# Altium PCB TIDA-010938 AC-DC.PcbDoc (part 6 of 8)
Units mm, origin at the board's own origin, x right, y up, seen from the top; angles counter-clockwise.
Board outline 280 x 180.15 mm, 4 copper layers (Top Layer, Layer 1, Layer 2, Bottom Layer), stack 1.787 mm thick; 723 components, 427 nets, 2244 pads, 2295 vias.
Unrouted connection lines stored in the file: 17.
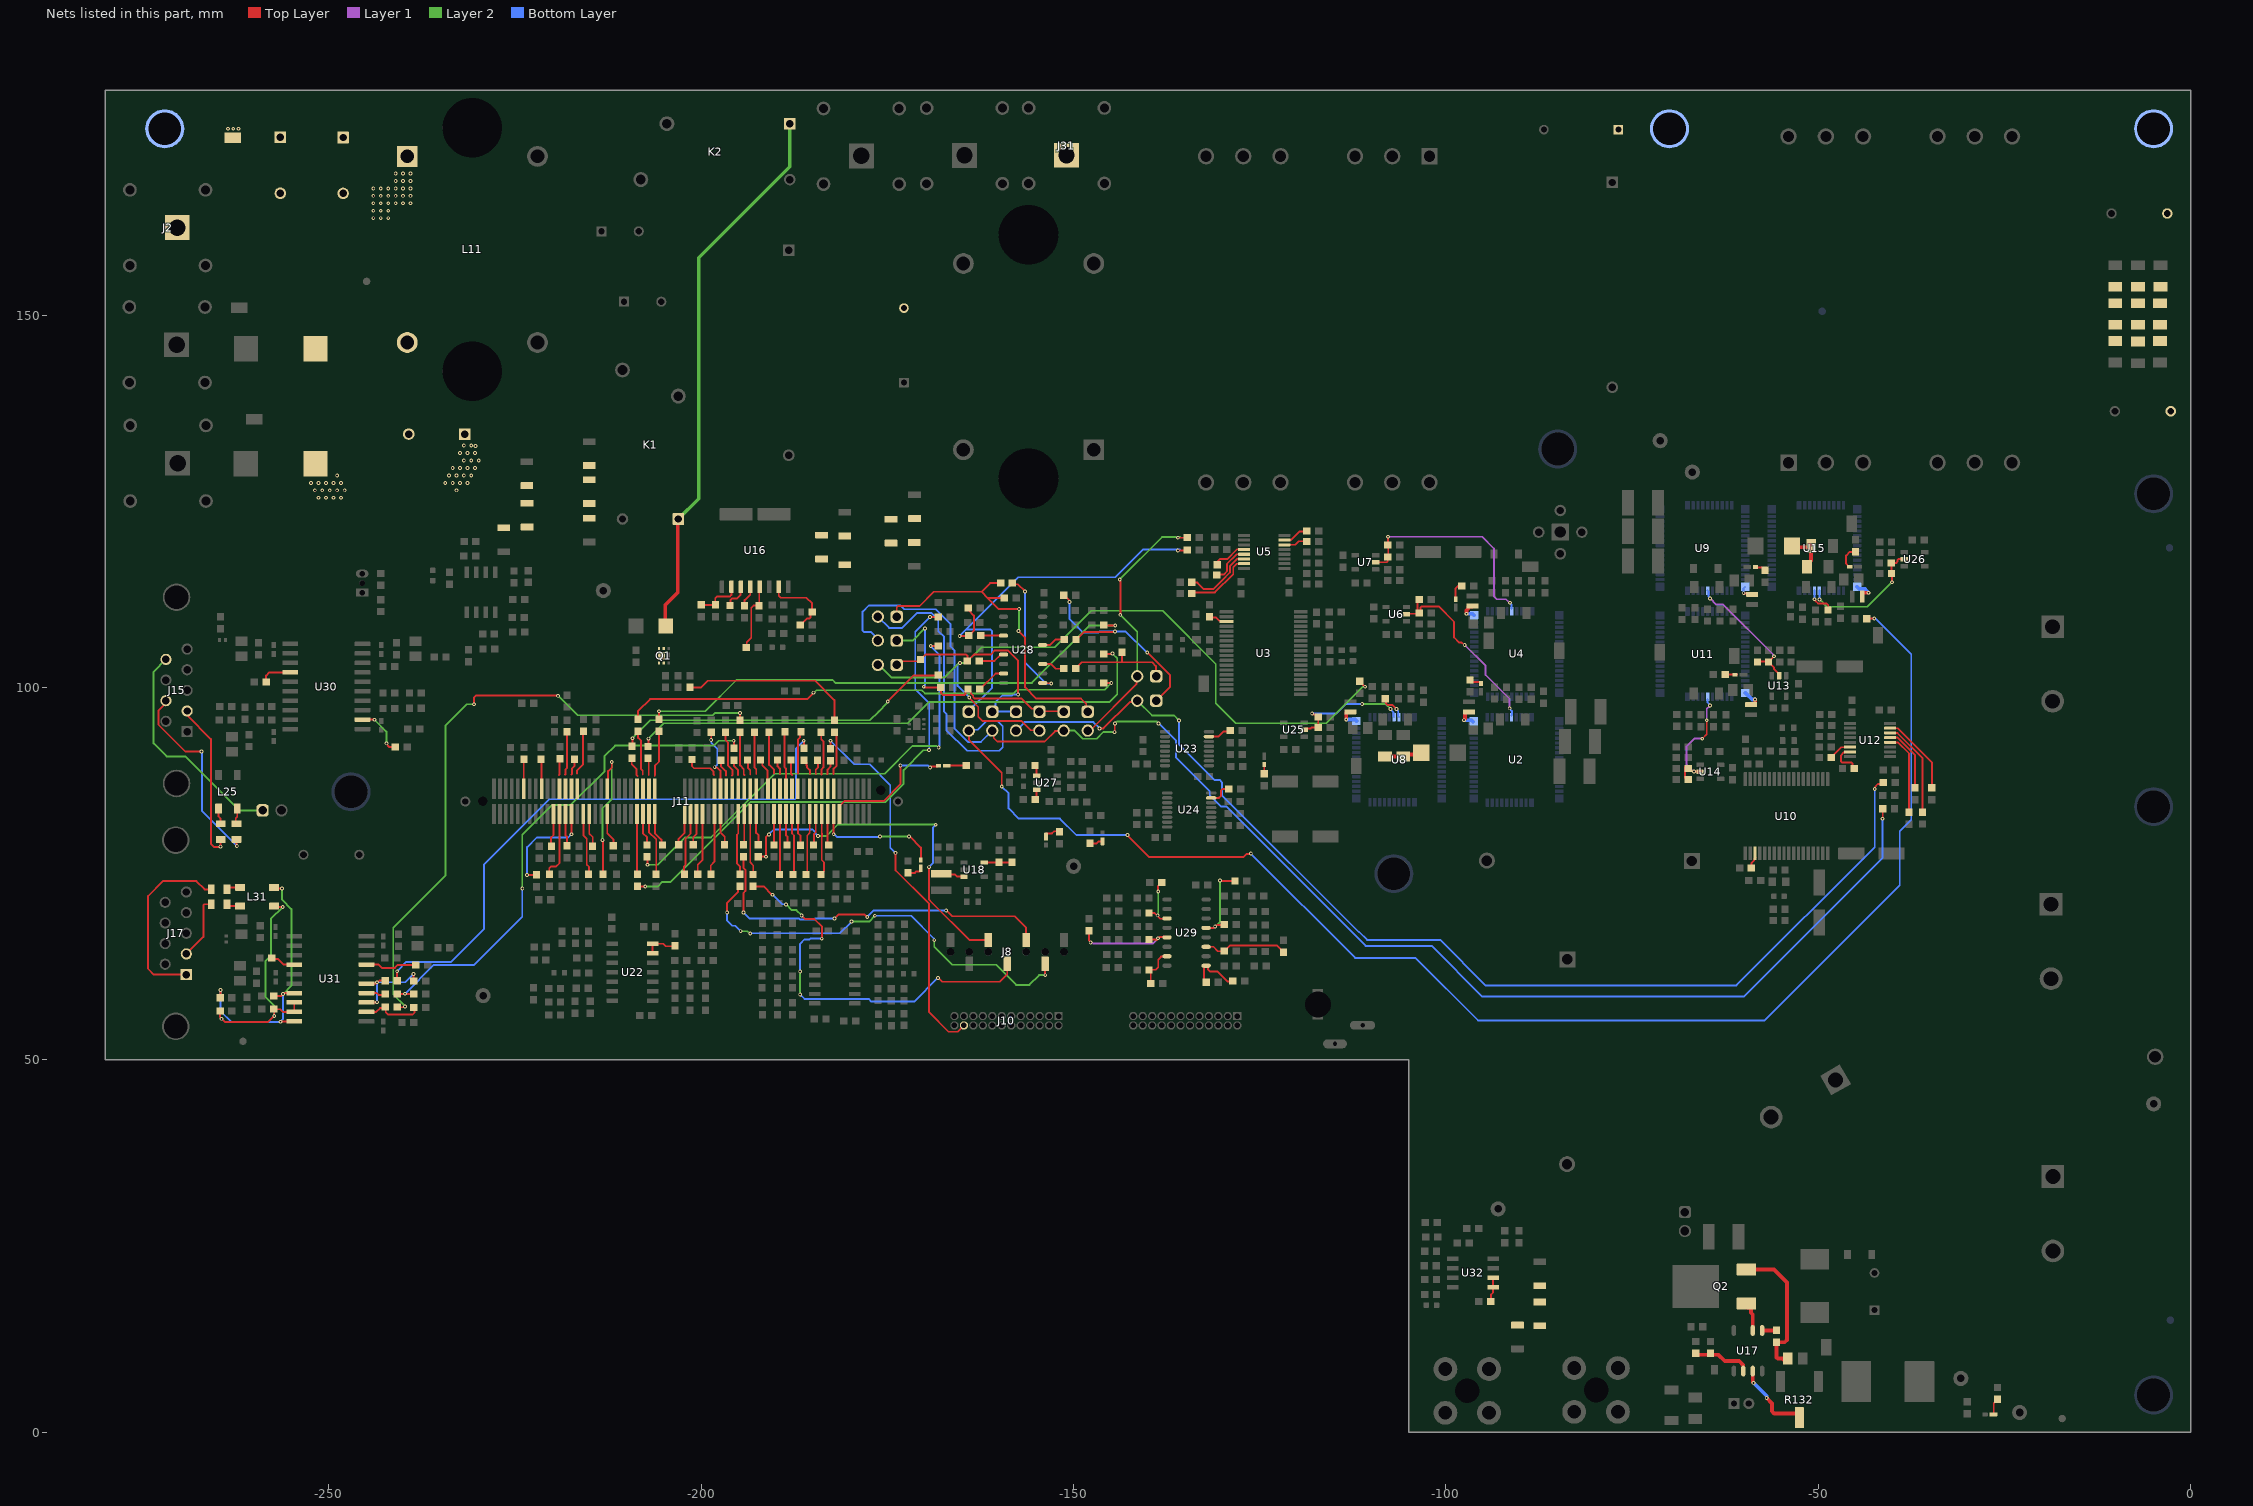
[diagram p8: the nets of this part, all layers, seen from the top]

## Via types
v1: diameter 0.508, hole 0.254, Top Layer to Bottom Layer, tented both sides, 2041 vias
v2: diameter 0.508, hole 0.254, Top Layer to Bottom Layer, 252 vias
v3: diameter 0.5, hole 0.2, Top Layer to Bottom Layer, 2 vias

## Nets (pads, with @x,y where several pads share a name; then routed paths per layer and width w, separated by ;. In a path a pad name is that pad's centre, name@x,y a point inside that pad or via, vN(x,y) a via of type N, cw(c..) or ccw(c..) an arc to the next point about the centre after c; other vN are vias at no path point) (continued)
NetC233_2: C233.2 L31.1 R288.2 U31.18 U31.19 | length 30.1
  Top Layer w0.25: C233.2@-264.578,56.566 -264.578,55.722 -263.956,55.1 -258.1,55.1 v1(-257.3,55.9) -257.3,56.47 -257.43,56.6 R288.2@-257.5,56.6 ; R288.2@-257.352,56.82 -257.332,56.8 -256.5,56.8 -256.139,56.439 -255.545,56.439 -255.5,56.484 U31.19@-255.5,56.5 ; L31.1@-257.325,70.65 -257.196,70.521 v1(-256.158,70.521) ; U31.18@-254.62,57.709 -254.62,56.52 U31.19@-254.6,56.5
  Layer 2 w0.25: v1(-257.3,55.9) -257.3,57.3 -258.492,58.492 -258.492,63.258 -257.75,64 -257.75,68.929 v1(-256.158,70.521)
  other v1: -264.374,55.517
NetC234_2: C234.2 R320.2 U31.3 U31.5 | length 13.1
  Top Layer w0.25: U31.3@-244.92,57.709 -243.509,57.709 v1@-243.5,57.7 ; U31.5@-244.92,60.249 -243.599,60.249 -243.198,60.65 -242.525,60.65 R320.2@-242.475,60.6 ; v1@-238.6,61.475 -238.6,60.607 C234.2@-238.59,60.597
  Bottom Layer w0.25: v1(-243.525,57.75) -243.513,57.763 -243.513,60.488 v1@-243.5,60.5 ; v1(-243.5,60.425) -239.725,60.425 v1(-238.6,61.55) v1@-238.6,61.6
NetC235_2: C235.2 R323.2 U31.2 | length 7.9
  Top Layer w0.25: U31.2@-244.92,56.439 -243.614,56.439 -243.1,56.953 R323.2@-242.547,56.953 ; R323.2@-242.404,57.074 -242.325,56.995 -242.325,56.375 -242.025,56.075 -238.75,56.075 -238.475,56.35 C235.2@-238.475,56.8
NetC237_1: C237.1 L31.2 R289.1 U31.17 U31.20 | length 36.6
  Top Layer w0.25: C237.1@-264.578,58.344 -264.5,58.422 v1(-264.5,59.4) ; R289.1@-257.39,58.598 -256.302,58.598 -255.9,59 U31.17@-255.4,59 ; L31.2@-257.325,73.15 -257.175,73 v1(-256.25,73) ; v1@-256.4,55.1 -256.331,55.169 U31.20@-254.62,55.169
  Layer 2 w0.25: v1(-256.25,73) -256.25,71.5 -255,70.25 -255,59.952 v1(-256.123,58.828)
  Bottom Layer w0.25: v1(-264.5,59.4) -264.5,56.5 -263.1,55.1 v1@-256.5,55.1 ; v1@-256.5,55.2 -256.461,55.2 -256.123,55.537 v1(-256.123,58.828)
  other v1: -256.474,55.117
NetD1_2: D1.2 R7.2 R41.2 | length 5.1
  Top Layer w0.25: R7.2@-105.75,90.725 R7.2@-105.475,91 ; D1.2@-103.55,91 D1.2@-103.325,91.225
  Top Layer w0.5: R41.2@-108.2,90.725 R7.2@-105.75,90.725 ; R7.2@-105.475,91 D1.2@-103.55,91
NetD4_2: D4.2 R17.2 | length 1.7
  Top Layer w0.25: R17.2@-96.8,101 -96.55,100.75 -95.425,100.75 -95.3,100.625 D4.2@-95.3,100.545
NetD7_2: D7.2 R53.2 R55.2 | length 5.2
  Top Layer w0.5: D7.2@-53.29,118.721 -53.19,118.821 -51,118.821 -51,117.011 -51.54,116.471 R53.2@-51.54,116.196
NetD10_2: D10.2 R42.2 | length 2.4
  Top Layer w0.25: D10.2@-98.7,111.845 -98.7,113.3 -98.4,113.6 R42.2@-97.9,113.6
NetD16_1: D16.1 R100.1 | length 2.4
  Top Layer w0.25: D16.1@-26.459,2.399 -26.459,3.92 R100.1@-25.851,4.528
NetD17_1: D17.1 R101.2 | length 1.8
  Top Layer w0.25: D17.1@-153.7,80.3 -153.6,80.4 -152.9,80.4 -152.6,80.7 R101.2@-152.1,80.7
NetD18_1: D18.1 R102.2 | length 1.8
  Top Layer w0.25: R102.2@-147.8,79.075 -146.879,79.075 -146.617,79.337 D18.1@-146.117,79.337
NetD23_1: D23.1 R70.2 | length 1.8
  Top Layer w0.25: R70.2@-172.2,75.1 -171.3,75.1 -171.1,75.3 -170.6,75.3 D23.1@-170.5,75.4
NetD23_2: D23.2 J11.107 | length 16.7
  Top Layer w0.25: J11.107@-182.207,82.998 -182.204,82.995 -182.204,80.303 v1(-182.2,80.3) ; v1@-172,80 -170.5,78.5 D23.2@-170.5,77
  Layer 2 w0.25: v1(-175.975,79.975) v1(-172.075,79.975) -172.025,79.975 v1@-172,80
  Bottom Layer w0.25: v1(-182.2,80.3) -182.13,80.3 -181.776,79.946 v1@-175.954,79.946
NetD24_1: D24.1 R76.2 | length 2.7
  Top Layer w0.25: D24.1@-167.03,89.5 R76.2@-164.379,89.5
NetD24_2: D24.2 J11.109 | length 18.4
  Top Layer w0.25: J11.109@-181.407,82.998 -181.407,84.093 -180.75,84.75 -175.5,84.75 -173.25,87 v1(-173.25,89.504) ; v1(-169.25,89.25) -169.18,89.25 -169.023,89.408 -168.237,89.408 D24.2@-168.145,89.5 D24.2@-168.245,89.5
  Bottom Layer w0.25: v1(-173.25,89.504) -169.504,89.504 v1(-169.25,89.25)
NetD25_2: D25.2 R43.2 | length 1.3
  Top Layer w0.25: R43.2@-124.4,88.4 D25.2@-124.4,89.655
NetD26_2: D26.2 R51.2 | length 1.2
  Top Layer w0.25: D26.2@-58.19,116.121 -57.69,116.121 -57.665,116.096 -57.54,116.096 -57.29,115.846 -57.29,115.721 R51.2@-57.19,115.721
NetD27_2: D27.2 R52.2 | length 1.6
  Top Layer w0.25: R52.2@-62.79,101.721 R52.2@-62.785,101.721 ; R52.2@-62.49,101.721 D27.2@-60.935,101.721
NetD28_2: D28.2 R115.2 | length 3.2
  Top Layer w0.25: D28.2@-45.805,116.221 -45.905,116.221 -46.29,116.606 -46.29,117.71 -45.8,118.2 R115.2@-45,118.2
NetF1_1: F1.1 L11.AII R78.2 R82.2
NetF2_1: F2.1 L11.AI R81.2 R82.1
  other v1: -244,163 -243,163 -242,163 -244,164 -243,164 -242,164 -244,165 -243,165 -242,165 -241,165 -240,165 -239,165 -244,166 -243,166 -242,166 -241,166 -240,166 -239,166 -244,167 -243,167 -242,167 -241,167 -240,167 -239,167 -241,168 -240,168 -239,168 -241,169 -240,169 -239,169
  other v2: -251.352,125.464 -250.352,125.464 -249.352,125.464 -248.352,125.464 -251.852,126.464 -250.852,126.464 -249.852,126.464 -248.852,126.464 -247.852,126.464 -232.852,126.464 -252.352,127.464 -251.352,127.464 -250.352,127.464 -249.352,127.464 -248.352,127.464 -234.352,127.464 -233.352,127.464 -232.352,127.464 -231.352,127.464 -248.852,128.464 -233.852,128.464 -232.852,128.464 -231.852,128.464 -230.852,128.464 -233.352,129.464 -232.352,129.464 -231.352,129.464 -230.352,129.464 -231.852,130.464 -230.852,130.464 -229.852,130.464 -232.352,131.464 -231.352,131.464 -230.352,131.464 -230.298,132.434 -231.852,132.464 -230.852,132.464
NetJ4_1: J4.1 J21.1 J23.1 R146.2 R249.2 | length 31.3
  Top Layer w0.25: J4.1@-173.73,103.525 -170.775,103.525 R249.2@-170.55,103.75 -170.55,103.775 -170.2,104.125 -170.175,104.125 -169.881,104.419 -164.404,104.419 -164.258,104.273 R146.2@-164.258,103.556 -164.233,103.556 -163.37,104.419 -161.115,104.419 -160.569,104.965 -158.822,104.965 -157.451,103.594 -157.451,99.089 v1(-157.43,99.068) ; J21.1@-161.413,96.749 J21.1@-161.375,96.787
  Bottom Layer w0.25: J23.1@-158.256,97.283 J23.1@-158.243,97.296 ; J23.1@-157.721,96.749 J21.1@-160.913,96.749 -160.5,97.162 -160.5,98 -159.578,98.922 -158.256,98.922 -158.109,99.068 v1(-157.43,99.068)
NetJ5_1: J5.1 R154.2 R243.2 | length 14.5
  Top Layer w0.25: R154.2@-149.729,102.565 -149.704,102.565 -148.891,103.378 -143.532,103.378 ; R243.2@-143.5,104.5 -143.5,103.41 -143.532,103.378 ; J5.1@-138.934,100.889 -138.934,102.878 -139.434,103.378 -143.532,103.378
NetJ8_2: J8.2 R57.1 | length 56.2
  Top Layer w0.25: v1@-196.5,69.8 -196.5,71.1 -195.029,72.571 -195.029,73.071 R57.1@-194.8,73.3 ; J8.2@-153.82,62.9 -153.82,61.42 v1@-153.8,61.4
  Layer 2 w0.25: v1(-194.684,67.28) -193.774,67.28 -193.493,67 v1@-193.4,67 ; v1@-179.79,68.574 -177.449,68.574 v1(-176.675,69.349) ; v1(-168.698,66.074) -168.698,65.198 -166.272,62.772 -160.406,62.772 -157.705,60.071 -155.927,60.071 -154.624,61.374 v1(-153.798,61.374)
  Bottom Layer w0.25: v1(-196.498,69.774) -196.498,68.698 -195.814,68.014 -195.417,68.014 v1(-194.684,67.28) ; v1(-193.398,66.974) -193.369,67.003 -181.369,67.003 v1(-179.798,68.574) ; v1(-176.675,69.349) -171.801,69.349 -168.747,66.295 -168.747,66.124 v1(-168.698,66.074)
NetJ8_3: J8.3 R210.1 | length 49.4
  Top Layer w0.25: R210.1@-194.325,77.3 -194.325,75.789 -194.05,75.514 -194.05,72.686 -194.3,72.436 v1@-194.3,69.8 ; v1(-182.098,68.974) -181.572,69.5 -178.024,69.5 v1(-177.698,69.174) ; v1@-167.1,70.1 -166.281,69.281 -157.881,69.281 -156.36,67.76 J8.3@-156.36,66.105
  Bottom Layer w0.25: v1(-194.298,69.774) -193.528,69.004 -186.876,69.004 -186.717,68.845 -184.807,68.845 -184.648,69.004 -182.104,69.004 v1@-182.1,69 ; v1@-177.7,69.2 -176.826,70.074 v1(-167.098,70.074)
NetJ8_4: J8.4 R212.1 | length 54.6
  Top Layer w0.25: R212.1@-193.02,73.291 -191.618,73.291 -190.527,72.2 v1@-190.4,72.2 ; v1(-186.498,69.374) -186.024,68.9 -184.776,68.9 -183.765,67.889 -183.765,66.335 v1@-183.8,66.3 ; v1(-168.2,61) -168.134,61 -167.634,60.5 -159.9,60.5 -158.9,61.5 J8.4@-158.9,62.9
  Layer 2 w0.25: v1(-188.598,70.874) -187.836,70.112 -187.212,70.112 v1@-186.5,69.4 ; v1@-186.7,61.9 -186.698,61.898 v1(-186.698,61.874) v1(-186.698,58.774)
  Bottom Layer w0.25: v1(-190.398,72.174) -189.124,70.9 v1@-188.6,70.9 ; v1(-186.698,58.774) -186.115,58.191 -177.517,58.191 -177.161,57.836 -171.364,57.836 v1(-168.2,61) ; v1(-186.698,61.874) -186.698,65.602 -186.136,66.164 -185.456,66.164 -185.346,66.274 v1(-183.798,66.274)
NetJ8_5: J8.5 R214.1 | length 48.6
  Top Layer w0.25: R214.1@-192.325,77.3 v1@-191.3,77.3 ; v1(-191.298,77.274) -191.298,79.902 v1@-190.9,80.3 ; v1(-169.398,75.874) -169.398,71.5 -169,71.102 ; -169,71.1 -169,71.102 ; J8.5@-161.44,66.105 -164.003,66.105 -168.999,71.101
  Layer 2 w0.25: v1(-184.321,80.042) -183.206,80.042 -181.648,81.6 v1@-168.5,81.6
  Bottom Layer w0.25: v1(-190.898,80.274) -190.243,80.929 -185.029,80.929 -184.724,80.624 -184.724,80.515 -184.321,80.112 v1(-184.321,80.042) ; v1@-169.4,75.9 -168.846,76.454 -168.846,81.226 v1(-168.498,81.574)
NetJ11_12: J11.12 R174.1 | length 4
  Top Layer w0.25: J11.12@-223.807,86.398 -223.807,90.393 R174.1@-223.775,90.425
NetJ11_18: J11.18 R179.1 | length 4
  Top Layer w0.25: R179.1@-221.425,90.35 -221.407,90.332 J11.18@-221.407,86.398
NetJ11_21: J11.21 R183.1 | length 4.5
  Top Layer w0.25: R183.1@-220.125,78.675 -220.125,79.875 -219.807,80.193 J11.21@-219.807,82.998
NetJ11_23: J11.23 R182.1 | length 8.9
  Top Layer w0.25: R182.1@-220.425,75.2 -220.375,75.25 -220.375,75.7 -220.1,75.975 -219.45,75.975 -219.007,76.418 J11.23@-219.007,82.998 ; R182.1@-220.411,74.864 R182.1@-220.375,74.9 R182.1@-220.329,74.946
NetJ11_24: J11.24 R181.2 | length 2.3
  Top Layer w0.25: -219.1,88.225 -219.007,88.318 -219.007,90.368 R181.2@-218.95,90.425
NetJ11_25: J11.25 R184.1 | length 4.5
  Top Layer w0.25: J11.25@-218.207,82.998 -218.207,80.182 -218,79.975 -218,78.9 R184.1@-217.8,78.7 ; R184.1@-217.979,78.489 R184.1@-217.954,78.514
NetJ11_26: J11.26 R180.2 | length 5.8
  Top Layer w0.25: -218.25,88.3 -218.225,88.325 -218.225,88.975 -218.025,89.175 R180.2@-218.025,94.025
NetJ11_27: J11.27 R67.1 | length 14.4
  Top Layer w0.25: v1(-223.364,74.828) R67.1@-222.119,74.828 ; J11.27@-217.407,82.998 -217.407,80.302 v1(-217.395,80.289)
  Bottom Layer w0.25: v1(-223.364,74.828) -223.364,78.562 -222.068,79.858 -217.853,79.858 -217.421,80.289 v1(-217.395,80.289)
NetJ11_28: J11.28 R178.2 | length 2.3
  Top Layer w0.25: -217.425,88.275 -217.35,88.35 -217.35,89.1 -216.975,89.475 R178.2@-216.975,90.375
NetJ11_30: J11.30 R176.2 | length 6
  Top Layer w0.25: -216.65,88.45 -216.65,88.875 -215.85,89.675 -215.85,94.05 R176.2@-215.8,94.1
NetJ11_31: J11.31 R186.2 | length 7.9
  Top Layer w0.25: J11.31@-215.807,82.998 -215.807,80.132 -215.35,79.675 -215.35,76.2 -215.05,75.9 R186.2@-215.05,75.375
NetJ11_33: J11.33 R187.2 | length 4.4
  Top Layer w0.25: J11.33@-215.007,82.998 -215.007,80.382 -214.55,79.925 R187.2@-214.55,78.825
NetJ11_39: J11.39 R189.2 | length 4.4
  Top Layer w0.25: J11.39@-212.607,82.998 -212.607,80.407 -211.75,79.55 R189.2@-211.75,79
NetJ11_40: J11.40 R188.2 | length 19.4
  Top Layer w0.25: R188.2@-213.153,74.916 v1@-213.153,79.403 ; J11.40@-212.607,86.398 -212.482,86.523 -212.482,88.768 -212,89.25 v1(-212,90)
  Layer 2 w0.25: v1(-213.25,79.5) -213.25,83.75 -212,85 v1(-212,90)
NetJ11_49: J11.49 R190.2 | length 8.3
  Top Layer w0.25: R190.2@-208.65,75.025 -208.607,75.068 J11.49@-208.607,82.998 ; R190.2@-208.607,75.057 R190.2@-208.4,74.85
NetJ11_50: J11.50 R194.2 | length 2.7
  Top Layer w0.25: R194.2@-209.25,90.5 -209.3,90.45 -209.3,89.675 -208.65,89.025 -208.65,88.225 -208.55,88.125
NetJ11_51: J11.51 R192.2 | length 4.2
  Top Layer w0.25: J11.51@-207.807,82.998 -207.807,80.457 -207.25,79.9 R192.2@-207.25,79
NetJ11_52: J11.52 R196.2 | length 6.3
  Top Layer w0.25: R196.2@-208.45,94.4 -208.45,93.225 -208.05,92.825 -208.05,89.025 -207.825,88.8 -207.825,88.325
NetJ11_53: J11.53 R198.2 | length 8.3
  Top Layer w0.25: J11.53@-207.007,82.998 -207.007,80.582 -206.025,79.6 R198.2@-206.025,75.075
NetJ11_54: J11.54 R191.1 | length 2.3
  Top Layer w0.25: R191.1@-207.1,90.475 -207.025,90.4 -207.025,88.25
NetJ11_55: J11.55 R199.2 | length 4.5
  Top Layer w0.25: J11.55@-206.207,82.998 -206.207,80.457 -205.329,79.579 -205.329,79.004 R199.2@-205.225,78.9
NetJ11_56: J11.56 R193.1 | length 6.1
  Top Layer w0.25: -206.225,88.125 -206.207,88.143 ; -206.2,88.275 -206.2,89.475 -205.65,90.025 R193.1@-205.65,94.125
NetJ11_57: J11.57 R200.2 | length 4.2
  Top Layer w0.25: R200.2@-203.025,79.15 -203.025,79.675 -202.207,80.493 J11.57@-202.207,82.998
NetJ11_59: J11.59 R201.2 | length 8
  Top Layer w0.25: R201.2@-202.3,75.325 -202.3,75.95 -202.075,76.175 -202.075,79.725 -201.407,80.393 J11.59@-201.407,82.998
NetJ11_61: J11.61 R195.1 | length 4.4
  Top Layer w0.25: R195.1@-201.05,78.825 R195.1@-201.05,78.875 -201.05,79.9 -200.607,80.343 J11.61@-200.607,82.998
NetJ11_63: J11.63 R197.1 | length 8
  Top Layer w0.25: R197.1@-200.516,75.325 -200.516,75.334 -200.45,75.4 -200.45,76.204 -199.807,76.847 J11.63@-199.807,82.998
NetJ11_67: J11.67 R203.2 | length 8.2
  Top Layer w0.25: R203.2@-198.825,75.025 -198.7,75.15 -198.7,76.1 -198.207,76.593 J11.67@-198.207,82.998
NetJ11_68: J11.68 R204.1 | length 4.6
  Top Layer w0.25: R204.1@-201.219,90.326 -201.219,89.419 -200.95,89.15 -198.798,89.15 -198.329,88.681 -198.329,88.329 -198.225,88.225
NetJ11_69: J11.69 R205.2 | length 4.2
  Top Layer w0.25: J11.69@-197.407,82.998 -197.407,80.557 -196.825,79.975 R205.2@-196.825,79.025
NetJ11_70: J11.70 R206.1 | length 8.5
  Top Layer w0.25: v1@-198.65,93 -198.641,93.009 R206.1@-198.641,93.998 ; v1(-198.175,89.3) -198.126,89.251 -197.826,89.251 -197.407,88.832 J11.70@-197.407,86.398
  Layer 1 w0.25: v1(-198.65,92.95) v1@-198.643,92.943
  Bottom Layer w0.25: v1@-198.643,92.943 -198.643,92.568 -197.825,91.75 -197.825,89.65 v1(-198.175,89.3)
NetJ11_72: J11.72 R207.1 | length 2.3
  Top Layer w0.25: R207.1@-197.338,90.226 -197.338,89.438 -196.675,88.775 -196.675,88.175
NetJ11_74: J11.74 R208.1 | length 6.2
  Top Layer w0.25: R208.1@-196.699,93.976 -196.699,92.924 -196.375,92.6 -196.375,89.5 -195.807,88.932 -195.807,88.218 -195.875,88.15
NetJ11_75: J11.75 R57.2 | length 8.3
  Top Layer w0.25: J11.75@-195.007,82.998 -195.007,80.393 -195.2,80.2 -195.2,76.4 -194.8,76 R57.2@-194.8,74.9
NetJ11_76: J11.76 R209.1 | length 2.2
  Top Layer w0.25: R209.1@-195.56,90.226 -195.56,89.435 -195.022,88.897 -195.022,88.278 -195.075,88.225
NetJ11_77: J11.77 R210.2 | length 4
  Top Layer w0.25: J11.77@-194.207,82.998 -194.207,79.157 R210.2@-194.075,79.025
NetJ11_78: J11.78 R211.1 | length 6
  Top Layer w0.25: R211.1@-194.758,93.998 -194.758,89.533 -194.275,89.05 -194.275,88.325 -194.175,88.225
NetJ11_79: J11.79 R212.2 | length 7.9
  Top Layer w0.25: J11.79@-193.407,82.998 -193.407,76.507 -193,76.1 R212.2@-193,75.3
NetJ11_80: J11.80 R213.1 | length 2.1
  Top Layer w0.25: R213.1@-193.782,90.264 -193.725,90.207 -193.725,89.225 -193.4,88.9 -193.4,88.3
NetJ11_81: J11.81 R214.2 | length 4.2
  Top Layer w0.25: J11.81@-192.607,82.998 -192.607,80.484 -192.275,80.152 -192.275,79.125 R214.2@-192.4,79
NetJ11_82: J11.82 R215.1 | length 5.7
  Top Layer w0.25: R215.1@-192.816,93.998 -192.816,89.241 -192.6,89.025 -192.6,88.4
NetJ11_86: J11.86 R216.1 | length 4.3
  Top Layer w0.25: R216.1@-192.004,90.264 -191.785,90.045 -191.785,89.535 -191.105,88.855 -191.105,86.496 J11.86@-191.007,86.398
NetJ11_87: J11.87 R217.2 | length 3.9
  Top Layer w0.25: R217.2@-190.225,79.1 -190.207,79.118 J11.87@-190.207,82.998
NetJ11_88: J11.88 R218.1 | length 5.8
  Top Layer w0.25: R218.1@-190.875,93.975 -190.875,89.6 -190.2,88.925 -190.2,88.425
NetJ11_89: J11.89 R219.2 | length 8
  Top Layer w0.25: R219.2@-189.475,75.075 -189.407,75.143 J11.89@-189.407,82.998
NetJ11_90: J11.90 R220.1 | length 2
  Top Layer w0.25: R220.1@-189.718,90.264 -189.718,89.393 -189.425,89.1 -189.425,88.375
NetJ11_91: J11.91 R221.2 | length 4.1
  Top Layer w0.25: J11.91@-188.607,82.998 -188.607,80.182 -188.4,79.975 R221.2@-188.4,79
NetJ11_92: J11.92 R222.1 | length 7.8
  Top Layer w0.25: J11.92@-188.607,86.398 -188.607,89.102 -188.8,89.295 -188.8,93.775 R222.1@-188.55,94.025
NetJ11_93: J11.93 R223.2 | length 8
  Top Layer w0.25: J11.93@-187.807,82.998 -187.807,80.407 -187.525,80.125 -187.525,75.266 -187.566,75.225 R223.2@-187.65,75.225
NetJ11_94: J11.94 R224.1 | length 2.1
  Top Layer w0.25: R224.1@-187.94,90.264 -187.94,88.405 -187.785,88.25 -187.775,88.25
NetJ11_95: J11.95 R225.2 | length 4.1
  Top Layer w0.25: J11.95@-187.007,82.998 -187.007,80.457 -186.675,80.125 R225.2@-186.675,79.075
NetJ11_96: J11.96 R226.1 | length 5.8
  Top Layer w0.25: -187,88.425 -187,93 -186.704,93.296 -186.704,93.93 R226.1@-186.609,94.025
NetJ11_99: J11.99 R227.2 | length 8.3
  Top Layer w0.25: R227.2@-185.85,74.85 -185.75,74.95 -185.75,80.125 -185.407,80.468 J11.99@-185.407,82.998
NetJ11_100: J11.100 R228.1 | length 2.1
  Top Layer w0.25: R228.1@-186.162,90.226 -185.839,89.903 -185.839,89.544 -185.803,89.508 -185.803,89.298 -185.4,88.895 -185.4,88.4
NetJ11_101: J11.101 R229.2 | length 4
  Top Layer w0.25: R229.2@-184.85,79.1 -184.85,80.325 -184.607,80.568 J11.101@-184.607,82.998
NetJ11_102: J11.102 R230.1 | length 1.9
  Top Layer w0.25: -184.575,88.35 -184.607,88.382 -184.607,88.943 -184.325,89.225 R230.1@-184.325,90.1
NetJ11_103: J11.103 R231.2 | length 8.4
  Top Layer w0.25: R231.2@-183.9,74.975 -183.817,74.975 -183.526,75.266 -183.526,75.386 -183.5,75.412 -183.5,76.527 -183.807,76.834 -183.807,79.917 -183.769,79.955 -183.769,80.393 -183.807,80.431 J11.103@-183.807,82.998
NetJ11_104: J11.104 R232.1 | length 5.9
  Top Layer w0.25: R232.1@-183.876,93.998 -183.876,93.051 -183.575,92.75 -183.575,89.275 -183.825,89.025 -183.825,88.325
NetJ11_105: J11.105 R233.2 | length 3.9
  Top Layer w0.25: J11.105@-183.007,82.998 -183.007,79.207 R233.2@-182.925,79.125
NetJ11_106: J11.106 R234.1 | length 2
  Top Layer w0.25: -183.075,88.375 -183.047,88.375 -183.025,88.397 -183.025,88.975 -182.65,89.35 -182.65,90.144 R234.1@-182.606,90.188
NetJ11_108: J11.108 R236.1 | length 5.9
  Top Layer w0.25: -182.25,88.375 -182.222,88.375 -182.2,88.397 -182.2,89.1 -181.8,89.5 -181.8,93.7 R236.1@-182.098,93.998
NetJ13_1: J13.1 R175.2 R241.2 | length 30.1
  Top Layer w0.25: R241.2@-151.3,112.375 -151.275,112.375 -150.596,111.696 -150.596,111.516 v1(-150.547,111.467) ; R175.2@-149.666,106.426 -149.641,106.426 -148.625,107.442 v1@-144.471,107.442 ; v1(-140.107,104.711) -137.029,101.632 -137.029,100.101 J13.1@-138.909,98.222
  Bottom Layer w0.25: v1(-150.547,111.467) -150.547,109.214 -148.7,107.367 -146.679,107.367 -146.541,107.505 v1(-144.451,107.505) -142.985,107.505 v1@-140.128,104.648
NetJ14_1: J14.1 J24.1 J25.1 R148.2 R247.2 | length 33.7
  Top Layer w0.25: v1(-170.112,100.091) -170.043,100.091 -169.951,100 R247.2@-167.8,100 ; R247.2@-167.816,99.67 -167.796,99.65 -167.796,99.296 -167.475,98.975 -164.646,98.975 -164.499,99.121 -164.499,99.466 R148.2@-164.169,99.797 -164.144,99.797 -163.794,99.447 -163.794,99.2 -163.471,98.877 -163.471,98.673 -163.325,98.527 -157.027,98.527 -155.633,97.133 -154.913,97.133 -154.579,96.799 -151.361,96.799 J25.1@-151.311,96.749
  Layer 2 w0.25: J14.1@-173.73,106.3 -171.576,106.3 v1(-169.948,107.928)
  Bottom Layer w0.25: v1(-170.112,100.091) -170.112,100.161 -169.954,100.319 -169.954,107.842 v1@-169.922,107.874
NetJ15_2: J15.2 R316.2 | length 21.2
  Top Layer w0.25: J15.2@-268.999,96.838 -268.999,96.261 -265.8,93.062 -265.8,79 -265.4,78.6 v1@-264.7,78.6 ; v1@-264.5,78.8 -264.5,79.575 R316.2@-264.475,79.6
  other v1: -264.523,78.628
NetJ15_7: J15.7 R312.2 | length 26.4
  Top Layer w0.25: J15.7@-271.839,98.223 -271.839,97.885 -272.864,96.86 -272.864,95.029 -269.235,91.4 v1@-267,91.4 ; v1@-262.4,78.7 -262.375,78.725 R312.2@-262.375,79.6
  Bottom Layer w0.25: v1(-267.074,91.417) -267.025,91.367 -267.025,83.43 -262.4,78.805 v1@-262.4,78.8
  other v1: -262.323,78.728
NetJ15_9: J15.9 J16.1 | length 30.3
  Layer 2 w0.25: J15.9@-271.839,103.763 -273.5,102.102 -273.5,92.5 -271.75,90.75 -269.25,90.75 -262,83.5 J16.1@-258.87,83.5
NetJ17_1: J17.1 R325.2 | length 25
  Top Layer w0.25: J17.1@-269.105,61.46 -273.46,61.46 -274.25,62.25 -274.25,72 -272.25,74 -267.75,74 -266.65,72.9 R325.2@-265.75,72.9
NetJ17_2: J17.2 R321.2 | length 8.6
  Top Layer w0.25: J17.2@-269.105,64.23 -266.823,66.512 -266.823,70.754 -266.677,70.9 R321.2@-265.75,70.9
NetJ20_1: J20.1 J26.1 R152.2 R245.2 | length 45.9
  Top Layer w0.25: J20.1@-173.73,109.5 -173.73,110.77 -173.567,110.933 -170.665,110.933 -168.748,112.85 -162.35,112.85 ; R152.2@-159.8,114 -161.2,114 -162.35,112.85 ; R245.2@-159.3,112 -161.5,112 ; v1@-157.349,107.544 -156.5,106.694 -156.5,100 -155,98.5 -149,98.5 -148.302,97.802 -148.302,96.958 J26.1@-148.093,96.749 ; v1(-157.299,110.519) -160.019,110.519 -161.5,112 ; -162.35,112.85 -161.5,112
  Layer 2 w0.25: v1(-157.375,107.598) -157.337,107.636 -157.337,110.481 v1(-157.299,110.519)
NetL2_2: L2.2 U2.42 | length 3
  Top Layer w0.5: v1(-97.579,95.606) -97.579,95.608 -97.45,95.737 -97.45,96.65 -97.375,96.725 L2.2@-96.9,96.725
  Bottom Layer w0.5: v1(-97.579,95.606) -97.577,95.604 -96.571,95.604 U2.42@-96.375,95.408
NetL3_2: L3.2 U4.42 | length 2.7
  Top Layer w0.5: v1(-97.25,109.888) -97.248,109.89 -97.248,110.352 -97,110.6 -97,110.85 L3.2@-96.5,110.85
  Bottom Layer w0.5: v1(-97.25,109.888) -97.248,109.887 -96.412,109.887 U4.42@-96.225,109.7
NetL5_2: L5.2 U8.42 | length 3
  Top Layer w0.5: v1(-113.389,95.693) -113.389,95.696 -113.375,95.71 -113.375,96.65 -113.3,96.725 L5.2@-112.825,96.725
  Bottom Layer w0.5: v1(-113.389,95.693) -113.387,95.692 -112.21,95.692 U8.42@-112.018,95.5
NetL6_2: L6.2 U9.42 | length 2.2
  Top Layer w0.25: v1(-60.04,112.66) -59.99,112.611 -59.006,112.611 L6.2@-58.89,112.496
  Bottom Layer w0.25: v1(-60.04,112.66) -60.04,113.296 U9.42@-59.815,113.521
NetL7_2: L7.2 U11.42 | length 2.9
  Top Layer w0.5: L7.2@-59.04,97.696 -58.574,97.696 -58.499,97.771 -58.499,98.365 v1(-58.498,98.367)
  Bottom Layer w0.5: U11.42@-59.815,99.271 -59.79,99.271 -58.888,98.368 v1(-58.498,98.367) v1(-58.498,98.367)
NetL9_2: L9.2 U15.42 | length 3.2
  Top Layer w0.5: L9.2@-44.115,112.221 -44.115,112.646 -44.04,112.721 v1(-43.29,112.721)
  Bottom Layer w0.5: U15.42@-44.815,113.521 -44.515,113.221 -43.763,113.221 -43.75,113.207 -43.75,113.183 -43.29,112.723 v1(-43.29,112.721)
NetL14_1: L14.1 U18.3 | length 2.9
  Top Layer w0.25: L14.1@-167.766,74.981 -167.66,74.875 -165.875,74.875 -165.599,74.599 -165.049,74.599 U18.3@-165,74.55
NetL25_3: L25.3 R316.1 | length 1.9
  Top Layer w0.25: L25.3@-264.775,83.725 -264.775,82.675 -264.525,82.425 R316.1@-264.525,81.95
NetL25_4: L25.4 R312.1 | length 1.9
  Top Layer w0.25: R312.1@-262.45,81.95 -262.475,81.975 -262.475,82.45 -262.275,82.65 L25.4@-262.275,83.725
NetL31_3: L31.3 R325.1 | length 1.9
  Top Layer w0.25: R325.1@-263.709,72.922 -263.507,73.125 -261.9,73.125 L31.3@-261.875,73.15
NetL31_4: L31.4 R321.1 | length 1.7
  Top Layer w0.25: R321.1@-263.65,70.9 -263.425,70.675 -262.125,70.675 L31.4@-262.1,70.7
NetQ2_1: Q2.1 U17.6 | length 4.2
  Top Layer w0.5: Q2.1@-59.668,17.303 -59.545,16.753 -59.045,16.753 -59.045,16.046 -58.82,15.821 U17.6@-58.82,13.676
NetQ2_3: Q2.3 R96.2 R98.1 | length 18.7
  Top Layer w0.5: Q2.3@-59.668,21.863 -55.956,21.863 -54.221,20.129 -54.221,12.392 -54.514,12.099 R96.2@-55.621,12.099 -55.621,10.049 -55.471,9.899 -54.821,9.899 R98.1@-54.571,9.649
NetR1_1: R1.1 U32.1 U32.2 | length 3.3
  Top Layer w0.25: R1.1@-93.975,17.575 -93.975,18.475 -93.675,18.775 U32.1@-93.675,19.495 U32.2@-93.675,20.765
NetR8_1: R8.1 U5.7 | length 3.3
  Top Layer w0.25: U5.7@-121.675,119.788 -120.812,119.788 -119.675,120.925 R8.1@-118.8,120.925
NetR9_1: R9.1 U5.6 | length 3.1
  Top Layer w0.25: U5.6@-121.675,119.153 -120.222,119.153 -119.75,119.625 -118.925,119.625 R9.1@-118.85,119.55
NetR11_2: R11.2 U3.3 | length 2.1
  Top Layer w0.25: R11.2@-131.725,109.5 -131.625,109.4 -130.9,109.4 -130.45,108.95 -130.125,108.95 U3.3@-129.925,108.75
NetR18_1: R18.1 U12.7 | length 4.2
  Top Layer w0.25: U12.7@-46.352,91.356 -46.432,91.276 -46.575,91.276 -46.99,90.861 -46.99,90.092 -46.844,89.946 -45.59,89.946 -45.444,89.799 -45.444,89.446 -45.369,89.371 R18.1@-44.865,89.371
NetR19_1: R19.1 U12.6 | length 2.7
  Top Layer w0.25: R19.1@-48.29,90.596 -48.265,90.596 -47.915,90.946 -47.915,90.971 -46.915,91.971 U12.6@-46.165,91.971 ; U12.6@-45.97,91.991 U12.6@-45.965,91.996
NetR24_2: R24.2 U5.12 | length 4.1
  Top Layer w0.25: R24.2@-130.725,116.475 -130.65,116.55 -130.65,116.95 -130.375,117.225 -129.381,117.225 -128.056,118.55 U5.12@-127.75,118.55 ; R24.2@-130.55,116.5 R24.2@-130.525,116.475 ; U5.12@-127.154,118.489 U5.12@-127.125,118.518
NetR26_2: R26.2 U5.13 | length 5.2
  Top Layer w0.25: R26.2@-130.6,115.15 -129.85,115.15 -129.4,115.6 -129.4,116.59 -128.108,117.883 U5.13@-127.125,117.883
NetR28_2: R28.2 U5.14 | length 9.6
  Top Layer w0.25: R28.2@-134.1,114.125 -134.046,114.071 -133.371,114.071 -132.5,113.2 -131.234,113.2 -130.109,114.325 -129,115.434 -129,115.5 -128.975,115.525 -128.975,116.303 -128.828,116.45 -128.825,116.45 -128,117.275 -127.152,117.275 U5.14@-127.125,117.248
NetR31_2: R31.2 U5.15 | length 9.2
  Top Layer w0.25: R31.2@-134.1,112.6 -133.945,112.755 -131.03,112.755 -128.567,115.218 -128.567,116.142 -128.097,116.613 U5.15@-127.125,116.613
NetR37_2: R37.2 U8.49 | length 3.5
  Top Layer w0.25: R37.2@-108.15,98.5 -108.05,98.4 -108.05,97.85 -107.854,97.654 -107.204,97.654 -106.734,97.184 -106.716,97.184 v1@-106.7,97.2
  Bottom Layer w0.25: v1(-106.65,97.1) -106.65,97.03 -106.408,96.788 -106.408,96.125 U8.49@-106.308,96.025
NetR39_1: R39.1 U27.6 | length 1.5
  Top Layer w0.25: R39.1@-155.266,85.031 R39.1@-155.208,84.973 ; R39.1@-155.121,84.966 -154.95,85.137 U27.6@-154.95,86.275
NetR47_2: R47.2 U10.3 | length 1.7
  Top Layer w0.25: R47.2@-58.99,75.746 -58.99,76.411 -58.615,76.786 -58.615,76.996 U10.3@-58.44,77.171
NetR50_1: R50.1 U30.2 | length 6.9
  Top Layer w0.25: U30.2@-245.456,95.682 -245.45,95.676 -243.852,95.676 v1(-243.846,95.67) ; v1(-242.25,92.5) -242.25,92.43 -242.021,92.201 -242.021,92.158 -241.864,92 R50.1@-241.05,92
  Layer 2 w0.25: v1(-243.846,95.67) -242.25,94.074 v1(-242.25,92.5)
NetR58_2: R58.2 U12.12 | length 11.2
  Top Layer w0.25: U12.12@-40.34,92.626 -39.32,92.626 -37.84,91.146 -37.84,83.421 R58.2@-38.065,83.196
NetR61_2: R61.2 U12.13 | length 8.6
  Top Layer w0.25: U12.13@-40.34,93.261 -39.346,93.261 -37.04,90.955 R61.2@-37.04,86.571
NetR63_2: R63.2 U12.14 | length 12.5
  Top Layer w0.25: U12.14@-40.34,93.896 -40.312,93.867 -39.386,93.867 -36.015,90.496 R63.2@-36.015,83.721
NetR65_2: R65.2 U12.15 | length 10.7
  Top Layer w0.25: U12.15@-40.34,94.531 -39.35,94.531 -34.765,89.946 R65.2@-34.765,86.696
NetR71_2: R71.2 U15.49 | length 4.2
  Top Layer w0.25: v1(-50.515,111.846) -50.515,111.776 -50.369,111.63 -50.369,111.601 -50.059,111.292 -48.936,111.292 -48.69,111.046 -48.69,110.446 R71.2@-48.515,110.271
  Bottom Layer w0.25: U15.49@-50.525,112.996 -50.52,112.991 -50.52,111.851 v1(-50.515,111.846)
NetR73_1: R73.1 U27.4 | length 1.4
  Top Layer w0.25: R73.1@-155.219,89.456 -154.95,89.187 U27.4@-154.95,88.175
NetR77_1: R77.1 R79.1 R80.1 R185.2 R235.2 R290.2
NetR83_1: R83.1 U16.6 | length 2.8
  Top Layer w0.25: R83.1@-194.15,111.025 -194.15,111.725 -193.4,112.475 -193.4,113.501 U16.6@-193.385,113.516
NetR84_2: R84.2 R88.1 U16.4 | length 6.1
  Top Layer w0.25: R84.2@-199.978,111.079 -198.304,111.079 R88.1@-198.125,110.9 ; R88.1@-198.1,111.225 -198.1,112 -197.9,112.2 -196.15,112.2 -195.925,112.425 U16.4@-195.925,113.516
NetR85_2: R85.2 R87.1 U16.7 | length 8.9
  Top Layer w0.25: R85.2@-193.875,105.625 -193.875,106.05 -193.275,106.65 -193.275,110.675 -192.95,111 -192.275,111 R87.1@-192.25,110.975 ; R87.1@-192.2,111.125 -192.2,113.431 U16.7@-192.115,113.516
NetR86_2: R86.2 U16.5 | length 3.1
  Top Layer w0.25: R86.2@-196.075,111.425 -196.075,111.709 -195.855,111.93 -195.22,111.93 -194.7,112.45 -194.7,113.471 U16.5@-194.655,113.516
NetR91_2: R91.2 R92.2 U16.9 | length 9.8
  Top Layer w0.25: U16.9@-189.575,113.516 -189.575,112.3 -189.325,112.05 -185.875,112.05 -185.1,111.275 ; R91.2@-186.696,108.373 -186.671,108.373 -185.794,109.25 -185.5,109.25 -185.303,109.447 -185.303,109.952 -185.1,110.155 -185.1,111.25
NetR93_1: R93.1 R95.2 U17.2 | length 7.8
  Top Layer w0.5: R93.1@-66.471,10.599 -66.271,10.399 -63.409,10.399 -62.578,9.568 -60.639,9.568 -60.11,9.039 -60.11,8.245 U17.2@-60.09,8.226
NetR96_1: R96.1 U17.5 | length 1.9
  Top Layer w0.5: U17.5@-57.55,13.676 -57.539,13.688 -55.633,13.688 R96.1@-55.621,13.699
NetR99_2: R99.2 U30.14 | length 4.3
  Top Layer w0.25: R99.2@-258.4,100.75 -258.4,101.6 -257.968,102.032 U30.14@-255.156,102.032
NetR103_2: R103.2 R106.1 U18.5 | length 3.5
  Top Layer w0.25: U18.5@-161.958,76.499 -158.549,76.499 R103.2@-158.475,76.425
NetR108_2: R108.2 R109.1
NetR109_2: R109.2 R110.1
NetR111_2: R111.2 R112.1
NetR112_2: R112.2 R113.1
NetR116_2: R116.2 R117.1
NetR117_2: R117.2 R118.1
NetR122_2: R122.2 R123.1
NetR123_2: R123.2 R124.1
NetR125_1: R125.1 U31.7 | length 7
  Top Layer w0.25: U31.7@-244.92,62.789 -243.289,62.789 -242.854,62.354 -241.095,62.354 -240.698,62.75 R125.1@-238.3,62.75
NetR126_2: R126.2 U31.14 | length 3.4
  Top Layer w0.25: R126.2@-257.648,63.698 -257.502,63.552 -256.802,63.552 -256.039,62.789 U31.14@-254.62,62.789
NetR127_2: R127.2 R128.1
NetR128_2: R128.2 R129.1
NetR132_2: R132.2 U17.3 | length 10.6
  Top Layer w0.5: U17.3@-58.82,8.226 -58.82,6.75 v1(-58.721,6.649) v1(-58.721,6.649) ; v1(-56.947,4.597) -56.239,3.889 -56.239,2.833 -55.946,2.54 -52.898,2.54 -52.553,2.195 R132.2@-52.553,1.986
  Bottom Layer w0.5: v1(-58.721,6.649) -56.948,4.876 -56.948,4.599 v1(-56.947,4.597)
NetR144_1: R144.1 U28.3 | length 3.3
  Top Layer w0.25: R144.1@-162.291,107.136 R144.1@-162.442,106.985 -162.412,106.955 U28.3@-159.4,106.955
NetR146_1: R146.1 U28.5 | length 3.6
  Top Layer w0.25: R146.1@-162.658,103.556 -160.609,103.556 -159.75,104.415 U28.5@-159.4,104.415
NetR148_1: R148.1 U28.7 | length 4
  Top Layer w0.25: R148.1@-162.569,99.797 -162.544,99.797 -160.466,101.875 U28.7@-159.4,101.875
NetR152_1: R152.1 U28.9 | length 17.6
  Top Layer w0.25: R152.1@-158.2,114 -158.06,113.86 -157.471,113.86 v1(-156.5,112.888) ; U28.9@-154.15,100.605 -154.115,100.57 -153.029,100.57 v1(-152.994,100.535)
  Bottom Layer w0.25: v1(-156.5,112.888) -156.529,112.859 -156.529,103.381 -153.648,100.5 v1@-153,100.5
NetR154_1: R154.1 U28.11 | length 3.1
  Top Layer w0.25: U28.11@-154.15,103.145 -153.001,103.145 -152.371,102.514 -151.38,102.514 R154.1@-151.329,102.565
NetR170_1: R170.1 U22.13 U22.14 | length 4.6
  Top Layer w0.25: U22.13@-206.504,64.315 U22.14@-206.504,65.554 ; U22.14@-206.504,65.585 -205.11,65.585 -204.775,65.25 -203.375,65.25 R170.1@-203.3,65.175
NetR175_1: R175.1 U28.13 | length 3.2
  Top Layer w0.25: U28.13@-154.15,105.685 -153.176,105.685 -152.411,106.45 -151.29,106.45 R175.1@-151.266,106.426
NetR177_2: R177.2 U23.7 | length 3
  Top Layer w0.25: U23.7@-131.825,93.4 -131.787,93.438 U23.7@-131.2,93.438 ; U23.7@-131.2,93.4 -131.162,93.438 -130.512,93.438 -129.875,94.075 -129.3,94.075 R177.2@-129.175,94.2
NetR185_1: R185.1 R235.1 R290.1 R291.2 R326.2 R327.2
NetR202_2: R202.2 U24.7 | length 3.1
  Top Layer w0.25: U24.7@-131.525,85.175 -130.475,85.175 -130.225,85.425 -130.225,86.15 -130.025,86.35 R202.2@-129.35,86.35
NetR240_2: R240.2 R286.1 U29.13 | length 11.1
  Top Layer w0.25: U29.13@-132.2,67.725 -131.125,67.725 -130.75,68.1 -129.875,68.1 R286.1@-129.85,68.125 ; v1@-130.4,74.05 -130.375,74.025 R240.2@-128.325,74.025
  Layer 2 w0.25: v1@-131.011,67.839 -130.35,68.5 v1(-130.35,74.075)
  other v1: -130.986,67.914
NetR242_2: R242.2 R284.1 U29.11 | length 11.3
  Top Layer w0.25: U29.11@-132.2,65.185 -131.21,65.185 -130.619,64.594 R284.1@-129.8,64.594 ; R284.1@-129.783,64.602 -129.758,64.602 -129.008,65.352 -122.659,65.352 -122.157,64.85 -122.15,64.85 -121.8,64.5 R242.2@-121.8,64.475
NetR244_2: R244.2 R279.1 U29.9 | length 7.1
  Top Layer w0.25: R279.1@-132.2,60.425 -132.5,60.725 -132.5,62.506 -132.361,62.645 -132.07,62.645 -131.931,62.506 -131.931,62.131 -131.65,61.85 -130.661,61.85 -129.356,60.544 -128.819,60.544 R244.2@-128.75,60.475
NetR246_2: R246.2 R272.1 U29.7 | length 5.6
  Top Layer w0.25: R246.2@-139.625,60.25 -139.625,61.787 -139.9,62.062 R272.1@-139.867,62.095 -138.98,62.095 -138.625,62.45 -138.625,63.475 -138.243,63.857 -137.618,63.857 U29.7@-137.575,63.9
NetR248_2: R248.2 R264.1 U29.5 | length 13.2
  Top Layer w0.25: R248.2@-147.9,67.325 -147.9,66.02 -147.7,65.82 v1(-147.7,65.75) ; R264.1@-139.867,66.159 -138.791,66.159 -138.45,66.5 -137.925,66.5 U29.5@-137.85,66.575
  Layer 1 w0.25: v1(-147.7,65.75) -147.651,65.701 -147.479,65.701 -147.425,65.646 -139.329,65.646 v1(-138.65,66.325)
NetR250_2: R250.2 R259.1 U29.3 | length 7.6
  Top Layer w0.25: R259.1@-139.867,69.715 -139.115,69.715 -138.35,68.95 U29.3@-137.425,68.95 ; v1@-138.65,72.525 -138.65,73.35 -138.55,73.45 -138.55,73.475 -138.2,73.825 R250.2@-138.175,73.825
  Layer 2 w0.25: v1@-138.733,69.333 -138.625,69.44 v1(-138.625,72.6)
  other v1: -138.708,69.408
NetR319_2: R319.2 U31.4 | length 2.5
  Top Layer w0.25: U31.4@-244.92,58.979 -243.554,58.979 -243.3,58.725 -242.525,58.725 R319.2@-242.5,58.7
O\C\_S1: C246.2 R328.2 U2.48 U6.2 | length 26
  Top Layer w0.25: U6.2@-105.3,109.85 -105.25,109.9 -103.7,109.9 C246.2@-103.6,110 ; R328.2@-103.7,111.8 R328.2@-103.675,111.825 ; R328.2@-103.6,111.8 -103.8,111.6 -103.8,110.2 C246.2@-103.6,110 ; v1(-97.488,105.7) -97.558,105.7 -97.885,106.027 -98.227,106.027 -98.925,106.725 -98.925,108.825 -100.975,110.875 -103.279,110.875 -103.425,110.729 -103.425,110.175 C246.2@-103.6,110
  Layer 1 w0.25: v1(-97.488,105.7) -94.675,102.887 -94.675,101.675 -91.45,98.45 v1(-91.45,97.2)
  Bottom Layer w0.25: v1(-91.45,97.2) -91.45,97.13 -91.15,96.83 -91.15,96.3 U2.48@-91.2,96.25
O\C\_S2_init: C255.2 R337.2 U8.48 U25.2 | length 16.8
  Top Layer w0.25: U25.2@-119.051,94.329 -118.895,94.485 -118.176,94.485 -118.056,94.604 C255.2@-117.162,94.604 -117.15,94.616 R337.2@-117.15,96.025 -117.5,96.375 v1@-117.77,96.375
  Layer 2 w0.25: v1(-111.25,97.775) -108.1,97.775 v1(-107.45,97.125)
  Bottom Layer w0.25: v1(-117.965,96.5) -114.742,96.5 -113.467,97.775 v1(-111.25,97.775) ; v1(-107.45,97.125) -107.45,97.055 -107.058,96.663 -107.058,96.125 U8.48@-106.958,96.025
O\C\_S3: C250.2 R332.2 U9.48 U13.2 | length 17.5
  Top Layer w0.25: R332.2@-57.79,103.421 -57.715,103.496 C250.2@-56.69,103.496 ; C250.2@-56.69,103.421 -56.69,103.396 -56.653,103.358 -55.957,102.662 -55.957,102.471 -55.665,102.18 -55.665,102.171 -55.44,101.946 U13.2@-55.19,101.946 ; C250.2@-56.64,103.371 -56.34,103.671 -56.34,103.796 -55.966,104.17 v1(-55.966,104.19)
  Layer 1 w0.25: v1(-64.54,111.946) -63.715,111.121 -62.79,111.121 -56.095,104.425 -56.095,104.389 -55.966,104.26 v1(-55.966,104.19)
  Bottom Layer w0.25: U9.48@-64.875,112.996 -64.775,112.896 -64.775,112.25 -64.54,112.015 v1(-64.54,111.946)
O\C\_S4_init: C256.2 R338.2 U15.48 U26.2 | length 17.1
  Top Layer w0.25: C256.2@-40.219,116.729 C256.2@-40.19,116.729 ; v1@-40.19,114.171 -40.14,114.221 -40.14,115.271 R338.2@-40.19,115.321 C256.2@-40.19,116.729 ; U26.2@-38.74,117.246 -39.244,117.246 -39.39,117.099 -39.39,116.875 -39.537,116.729 C256.2@-40.19,116.729
  Layer 2 w0.25: v1(-49.84,111.821) -48.861,110.842 -43.419,110.842 v1(-40.14,114.121)
  Bottom Layer w0.25: U15.48@-49.875,112.996 -49.858,112.978 -49.858,111.838 v1(-49.84,111.821)
O\C\_S5: C248.2 R330.2 U4.48 U7.2 | length 29.6
  Top Layer w0.25: U7.2@-109.425,116.825 U7.2@-109.45,116.8 -107.971,116.8 -107.825,116.946 C248.2@-107.825,117.525 ; v1(-107.8,120.225) R330.2@-107.8,119.125 -107.75,119.075 C248.2@-107.75,117.65
  Layer 1 w0.25: v1(-107.8,120.225) -95.133,120.225 -93.561,118.654 -93.561,112.25 -93.161,111.85 -91.945,111.85 -91.47,111.375 v1(-91.4,111.375)
  Bottom Layer w0.25: v1(-91.4,111.375) -91.4,111.305 -91.2,111.105 U4.48@-91.2,110.6
O\C\_S6: C89.2 R34.2 U11.48 U14.2 | length 15.5
  Top Layer w0.25: R34.2@-67.89,87.821 C89.2@-67.89,89.321 ; C89.2@-67.69,89.121 -67.34,88.771 -66.81,88.771 -66.76,88.721 v1(-66.69,88.721) -66.665,88.696 -66.165,88.696 U14.2@-66.09,88.621 ; v1@-65.565,93.146 -64.995,93.716 v1(-64.995,95.599)
  Layer 1 w0.25: v1(-66.69,88.721) -66.76,88.721 -66.889,88.85 -66.919,88.85 -67.273,89.204 -67.69,89.621 -67.69,92.096 -66.615,93.171 v1@-65.643,93.171 ; v1(-64.995,95.599) -64.995,97.116 v1(-64.54,97.571)
  Bottom Layer w0.25: U11.48@-64.915,98.371 -64.89,98.346 -64.89,97.99 -64.54,97.64 v1(-64.54,97.571)
  other v1: -65.59,93.121
PE: J2.1 MP1.1 R78.1 R81.1 TP6.1 | length 0.1
  Top Layer w0.25: TP6.1@-262.886,173.787 TP6.1@-262.835,173.838
  other v1: -263.5,175 -262.8,175 -262.1,175
PE2: C102.2 C106.1 J31.1 MP2.1
PE3: C243.1 C244.2 MP4.1 | length 0.3
  Bottom Layer w0.25: C243.1@-2.698,137.084 C243.1@-2.478,137.304
PWM_S1: R190.1 R260.1 | length 68.3
  Top Layer w0.25: R190.1@-208.5,73.3 -208.475,73.275 v1(-207.5,73.275) ; v1@-169.3,109.4 -169.237,109.463 R260.1@-168.185,109.463
  Layer 2 w0.25: v1(-207.5,73.275) -205.823,73.275 -205.198,73.9 -204.073,73.9 -193.373,84.6 -175.3,84.6 -172.817,87.083 -172.817,88.916 -170.161,91.572 -169.43,91.572 v1(-169.4,91.602)
  Bottom Layer w0.25: v1(-169.4,91.602) -169.375,91.627 -169.375,97.875 -171.241,99.741 -171.241,107.484 v1@-169.3,109.425
  other v1: -169.275,109.45
PWM_S1_Buff: J22.1 R21.2 R22.1 R144.2 | length 56.5
  Top Layer w0.25: v1(-165.288,106.905) -164.122,106.905 R144.2@-164.042,106.985 -164.017,106.985 -163.375,107.627 -163.375,109.65 R21.2@-164.15,110.425 ; v1(-136,118.4) -134.775,118.4 R22.1@-134.75,118.425
  Bottom Layer w0.25: v1(-165.288,106.905) -165.288,106.912 -164.402,107.798 ; J22.1@-164.055,96.85 -160.926,99.979 -160.926,107.521 -161.202,107.798 -164.402,107.798 ; -135.7,118.5 -136,118.5 -140.7,118.5 -144.4,114.8 -157.4,114.8 -164.402,107.798
PWM_S2: R192.1 R265.1 | length 62
  Top Layer w0.25: R192.1@-207.244,77.251 -207.2,77.207 v1(-207.2,76.2) ; v1@-169.175,105.58 R265.1@-168.185,105.58
  Layer 2 w0.25: v1(-207.2,76.2) -205.823,76.2 -202.152,79.871 -198.668,79.871 -190.118,88.421 -175.356,88.421 -171.638,92.139 -168.359,92.139 -168.172,91.952 v1(-168.103,91.952)
  Bottom Layer w0.25: v1(-169.175,105.55) -168,104.375 -168,92.227 -168.053,92.174 -168.053,92.001 v1(-168.103,91.952)
PWM_S2_Buff: J4.2 J24.2 R35.1 | length 100.4
  Top Layer w0.25: v1(-164,98.658) -164,98.593 -162.785,97.377 -162.785,96.08 -162.183,95.479 -156.979,95.479 -155.759,94.259 -154.63,94.259 J24.2@-154.579,94.209 ; R35.1@-111.575,100.825 -111.575,100.8 -110.875,100.1 v1(-110.85,100.1)
  Layer 2 w0.25: J4.2@-176.634,103.529 -174.451,101.346 -167.281,101.346 -165.325,103.302 -164.437,103.302 -162.346,105.392 -152.533,105.392 -147.621,110.304 -138.054,110.304 -130.9,103.15 -130.9,97.877 -129.844,96.821 -128.223,95.2 -116.1,95.2 -111.2,100.1 v1@-110.8,100.1
  Bottom Layer w0.25: v1(-165.246,103.302) -165.282,103.302 -165.557,103.026 -165.557,100.215 v1(-164,98.658)
PWM_S3: R194.1 R268.1 | length 45.7
  Top Layer w0.25: v1(-209.225,93.175) -209.225,92.225 R194.1@-209.175,92.175 ; v1(-174.946,98.127) -171.449,101.624 -168.258,101.624 R268.1@-168.185,101.697
  Layer 2 w0.25: v1(-209.225,93.175) -206.8,95.6 -177.327,95.6 -176.176,96.751 -175.068,97.859 -175.068,97.936 -174.946,98.057 v1(-174.946,98.127)
PWM_S3_Buff: J14.2 J21.2 J25.2 R56.1 | length 193.9
  Top Layer w0.25: J21.2@-161.299,94.095 -161.245,94.095 -160.712,93.562 -160.712,93.212 -160.246,92.746 -153.859,92.746 -152.469,94.136 -151.383,94.136 J25.2@-151.311,94.209 ; v1(-144.5,94) -144.468,94.032 -144.468,95.139 v1(-144.436,95.171) ; v1@-41.365,82.321 R56.1@-41.365,83.696
  Layer 1 w0.25: J21.2@-160.913,93.913 J21.2@-160.913,94.209
  Layer 2 w0.25: J25.2@-151.311,94.209 -149.834,94.209 -148.734,93.109 -146.891,93.109 -145.98,94.02 v1@-144.5,94.02 ; v1(-144.436,95.171) -144.154,95.453 -138.855,95.453 -138.582,95.18 v1(-138.58,95.18)
  Bottom Layer w0.25: J14.2@-176.27,106.512 -177.221,107.463 -178.171,107.463 -178.317,107.61 -178.317,110.183 -177.5,111 -173.25,111 -172.75,110.5 -168.5,110.5 -166.5,108.5 -166.5,105.5 -166,105 -166,94.5 -164.198,92.698 -162.424,92.698 J21.2@-160.913,94.209 ; v1(-138.58,95.18) -136.225,92.825 -136.225,90.577 -131.719,86.071 -131.719,85.519 -130.229,84.029 -129.529,84.029 -110.8,65.3 -101.9,65.3 -95.1,58.5 -61.535,58.5 -61.507,58.527 -59.983,58.527 -41.415,77.096 v1(-41.415,82.371)
PWM_S4: R196.1 R273.1 | length 67.6
  Top Layer w0.25: R196.1@-208.425,95.775 -208.45,95.8 -208.45,96.85 -206.854,98.446 -185.754,98.446 v1(-184.9,99.3) ; R273.1@-145.943,100.602 -145.94,100.599 v1(-144.924,100.599)
  Layer 2 w0.25: v1(-184.9,99.3) -184.83,99.3 -184.506,99.624 -170.361,99.624 -169.924,99.187 -163.781,99.187 -163.76,99.166 -158.081,99.166 -157.547,99.7 -145.823,99.7 v1(-144.924,100.599)
PWM_S4_Buff: J20.2 J22.2 R69.1 | length 233.7
  Top Layer w0.25: J22.2@-164.055,94.31 J22.2@-164.055,94.209 -164.055,92.964 -159.635,88.544 v1(-159.635,86.69) ; v1@-142.767,80.128 -139.889,77.25 -127.154,77.25 -126.753,77.651 -126.249,77.651 v1(-126.2,77.7) ; R69.1@-43.49,109.221 -43.461,109.25 v1(-42.5,109.25)
  Bottom Layer w0.25: J20.2@-176.27,109.5 -174.77,108 -173,108 -171.021,109.979 -169.056,109.979 -168.153,109.076 -168.153,107.565 -167.385,106.797 -167.385,96.75 -167.075,96.44 -167.075,94.276 -164.299,91.5 -160,91.5 -159.5,92 -159.5,94.809 -160.146,95.455 -161.73,95.455 -162.855,94.33 -163.933,94.33 J22.2@-164.055,94.209 ; v1(-159.635,86.69) -158.721,85.776 -158.721,83.769 -157.349,82.398 -151.821,82.398 -149.614,80.191 v1(-142.746,80.191) ; v1(-126.2,77.7) -112.2,63.7 -104.1,63.7 -95.7,55.3 -57.211,55.3 -39.09,73.421 -39.09,80.671 -37.54,82.221 -37.54,104.471 v1@-42.29,109.221
PWM_S5: R191.2 R276.1 | length 73.2
  Top Layer w0.25: v1(-207.075,93.125) -207.075,92.275 R191.2@-207.025,92.225 ; R276.1@-145.943,104.485 -144.815,104.485 v1@-144.8,104.5
  Layer 2 w0.25: v1(-207.075,93.125) -205,95.2 -172.229,95.2 -169.359,98.069 -145.131,98.069 -144.14,99.06 -144.14,103.915 -144.7,104.475 v1@-144.7,104.594
  other v1: -144.775,104.55
PWM_S5_Buff: J5.2 J26.2 R20.1 | length 36
  Top Layer w0.25: J26.2@-148.093,94.209 -147.791,94.209 -141.554,100.446 -141.554,101.395 J5.2@-141.449,101.5 ; v1(-143.8,114.5) -143.751,114.451 -143.751,114.306 -143.7,114.255 v1@-143.7,109.9 ; v1(-136,120.1) -134.775,120.1 R20.1@-134.75,120.125
  Layer 2 w0.25: v1(-143.8,114.5) -138.1,120.2 -135.7,120.2 ; v1@-143.7,109.9 v1@-143.611,109.811 ; v1@-143.614,109.808 -143.676,109.746 -143.676,109.701 -141.449,107.474 J5.2@-141.449,101.5
  other v1: -143.725,109.75
PWM_S6: R193.2 R281.1 | length 68.9
  Top Layer w0.25: v1(-205.65,96.8) -205.65,95.9 R193.2@-205.6,95.85 ; R281.1@-145.943,108.368 -145.875,108.3 v1(-144.4,108.3)
  Layer 2 w0.25: v1(-205.65,96.8) -199.448,96.8 -195.248,101 -182.339,101 -181.959,100.62 -155.582,100.62 -147.902,108.3 v1(-144.4,108.3)
PWM_S6_Buff: J13.2 J23.2 R54.1 | length 154.1
  Top Layer w0.25: v1(-146.5,94.5) -146,94.5 -142.462,98.038 -141.633,98.038 J13.2@-141.449,98.222 ; v1(-42.44,86.371) -42.371,86.439 -42.371,86.685 -42.019,87.038 -41.473,87.038 R54.1@-41.29,87.221
  Layer 2 w0.25: J13.2@-141.449,98.222 -139.466,96.239 -136.514,96.239 v1(-135.825,95.55)
  Bottom Layer w0.25: J23.2@-158.089,93.84 -156.57,95.359 -147.339,95.359 -146.5,94.521 v1(-146.5,94.5) ; v1(-135.825,95.55) -135.825,92.325 -131.079,87.579 -130.394,87.579 -130.084,87.269 -130.084,85.536 -111.719,67.171 -111.671,67.171 -110.6,66.1 -100.8,66.1 -94.7,60 -61.011,60 -42.44,78.571 v1(-42.44,86.371)
RS485_D: R211.2 R323.1 | length 86.2
  Top Layer w0.25: R323.1@-240.804,57.074 -239.826,57.074 v1@-239.8,57.1 ; v1(-230.5,97.75) -230.5,98.63 -230.23,98.9 v1@-219.2,98.9 ; v1(-194.775,96.575) -194.758,96.558 R211.2@-194.758,95.576
  Layer 2 w0.25: v1(-239.734,57.186) -241.329,58.782 -241.329,67.734 -234.3,74.763 -234.3,94.9 -231.45,97.75 v1(-230.5,97.75) ; v1@-219.158,98.858 -216.571,96.271 -198.431,96.271 -198.127,96.575 v1(-194.775,96.575)
  other v1: -219.198,98.874
RS485_DE_R\E\: R228.2 R320.1 | length 78.7
  Top Layer w0.25: R320.1@-240.804,60.63 -240.8,60.634 v1(-240.8,61.9) ; v1@-186.2,92.8 -186.162,92.762 R228.2@-186.162,91.826
  Bottom Layer w0.25: v1(-240.8,61.9) -240.8,61.92 -239.574,63.146 -233.554,63.146 -229.152,67.548 -229.152,76.229 -220.38,85 -187.396,85 -187.25,85.146 -187.25,91.825 v1(-186.225,92.85)
RS485_R: C232.2 R209.2 R319.1 | length 68.8
  Top Layer w0.25: R319.1@-240.804,58.852 -238.752,58.852 C232.2@-238.7,58.8 ; v1@-195.6,92.7 -195.56,92.66 R209.2@-195.56,91.826
  Layer 2 w0.25: v1(-224,73) -224,80.198 -219.971,84.227 -217.475,84.227 -212.946,88.756 -212.946,90.804 -211.546,92.204 -198.296,92.204 -197.65,92.85 v1(-195.625,92.85)
  Bottom Layer w0.25: v1(-239.734,58.886) -235.874,62.746 -230.454,62.746 -224,69.2 v1(-224,73)
RY_DCPreCharge: J10.22 R234.2 | length 50.4
  Top Layer w0.25: R234.2@-182.606,91.788 v1@-182.606,92.85 ; v1(-173.9,77.8) -173.9,75.436 -169.4,70.936 -169.4,56.4 -166.785,53.785 -165.55,53.785 J10.22@-164.715,54.62
  Bottom Layer w0.25: v1@-182.7,92.9 -182.675,92.9 v1(-182.625,92.85) -179.463,89.688 -177.388,89.688 -174.6,86.9 -174.6,78.453 -173.947,77.8 v1(-173.9,77.8)
RY_PreCharge: R89.1 R236.2 | length 23.2
  Top Layer w0.25: R89.1@-201.5,100 -200,100 -199.098,100.902 -184.702,100.902 -182.1,98.3 R236.2@-182.1,95.925
SN_Relays_PreCharge: D13.2 K1.1 K2.1 Q1.1 Q1.2 Q1.5 Q1.6 Q1.8 | length 74.5
  Top Layer w0.5: D13.2@-204.8,108.1 -204.8,111.076 -203.15,112.726 -203.15,122.516 K1.1@-203.053,122.613
  Layer 2 w0.5: K1.1@-203.053,122.613 -200.326,125.34 -200.326,157.674 -188.091,169.909 K2.1@-188.091,175.683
